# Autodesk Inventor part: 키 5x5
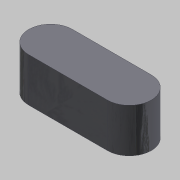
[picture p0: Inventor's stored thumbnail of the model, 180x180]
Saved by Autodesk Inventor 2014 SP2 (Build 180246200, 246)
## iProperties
Created: 2016-04
Part Number: 키 5x5
Document SubType Name: Modeling
Designer: mdu
Density: 7.86 g/cm^3
Mass: 2.54015 g
Surface Area: 2.9781 cm^2
Volume: 0.323175 cm^3
Material: 강철, 연강
Appearance: 강철 - 광택
Author: mdu
Revision Number: 1
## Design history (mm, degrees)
sketch "스케치1"
  geometry: L1 (-4.5, -2.5)-(4.5, -2.5); L2 (4.5, 2.5)-(-4.5, 2.5); A1 r 2.5 centre (4.5, 0) between (4.5, -2.5) and (4.5, 2.5); A2 r 2.5 centre (-4.5, 0) between (-4.5, 2.5) and (-4.5, -2.5); 2 further points
  constraints: 4 end point, 4 point on circle, 4 tangent, 2 centre point, 1 horizontal, 1 horizontal alignment, 1 midpoint, 1 parallel, 1 vertical alignment
  dimensions: "d0" = 5 distance between parallel lines of L1 L2; "d1" = 14 dimension on A1 A2
extrude "돌출1" new body sketch "스케치1" stored distance "d2" = 5; taper "d3" = 0 deg
node "솔리드1"
